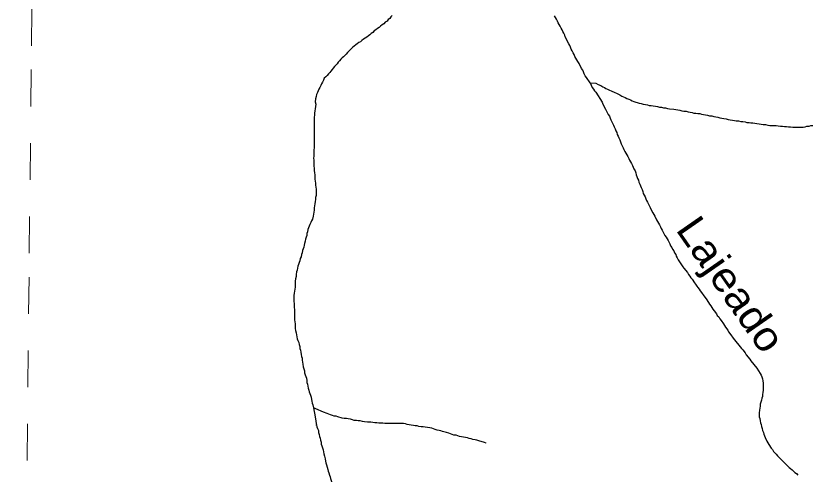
# Model space of a CAD drawing. Extents: x 652.3 to 678, y 7316.9 to 7344.9.
# Drawn here: x 652.343 to 654.508, y 7325.114 to 7326.361 of the extents above; entities that cross this region are included whole.
import ezdxf
from ezdxf.enums import TextEntityAlignment as Align

# ---------------------------------------------------------------- set-up
doc = ezdxf.new("R2010")
doc.units = 0
doc.header["$LTSCALE"] = 0.032
doc.linetypes.add('SHORT_DASHED', pattern=[2.7, 1.5, -1.2])
doc.layers.add('53', color=7, linetype='SHORT_DASHED', lineweight=13)
doc.layers.add('7', color=7, linetype='Continuous', lineweight=25)
doc.layers.add('61', color=7, linetype='Continuous')

msp = doc.modelspace()

# ---------------------------------------------------------------- linework, layer by layer
at = {"layer": '53'}
msp.add_lwpolyline([(652.343, 7322.3251), (652.3491, 7322.8901), (652.3551, 7323.4551), (652.3612, 7324.0202), (652.3672, 7324.5852), (652.3733, 7325.1502), (652.3794, 7325.7152), (652.3854, 7326.2802), (652.3915, 7326.8453), (652.3975, 7327.4103), (652.4036, 7327.9753), (652.4096, 7328.5403), (652.4157, 7329.1053), (652.4217, 7329.6703), (652.4278, 7330.2354), (652.4338, 7330.8004), (652.4399, 7331.3654), (652.4459, 7331.9304), (652.452, 7332.4954), (652.458, 7333.0604)], dxfattribs=at)
at = {"layer": '7'}
for points in [[(653.3671, 7326.3626), (653.3639, 7326.3586), (653.3608, 7326.3547), (653.3568, 7326.3515), (653.3536, 7326.3475), (653.3488, 7326.3443), (653.3448, 7326.3403), (653.3401, 7326.3372), (653.3361, 7326.3332), (653.3321, 7326.33), (653.3273, 7326.3268), (653.3234, 7326.3236), (653.3186, 7326.3204), (653.3146, 7326.3165), (653.3106, 7326.3133), (653.3067, 7326.3101), (653.3027, 7326.3069), (653.2987, 7326.3037), (653.2939, 7326.3006), (653.2891, 7326.2982), (653.2852, 7326.2942), (653.2812, 7326.291), (653.2764, 7326.2886), (653.2724, 7326.2854), (653.2685, 7326.2823), (653.2645, 7326.2791), (653.2605, 7326.2759), (653.2565, 7326.2727), (653.2533, 7326.2687)], [(653.9066, 7326.1796), (653.8963, 7326.1939), (653.8931, 7326.1987), (653.8907, 7326.2035), (653.8883, 7326.209), (653.8867, 7326.2138), (653.8835, 7326.2178), (653.8764, 7326.2321), (653.8732, 7326.2369), (653.8708, 7326.2417), (653.8676, 7326.2464), (653.8652, 7326.2512), (653.8628, 7326.256), (653.8605, 7326.2608), (653.8573, 7326.2663), (653.8549, 7326.2711), (653.8533, 7326.2759), (653.8509, 7326.2807), (653.8485, 7326.2854), (653.839, 7326.3045), (653.8374, 7326.3093), (653.835, 7326.3141), (653.8318, 7326.3189), (653.8302, 7326.3236), (653.8278, 7326.3284), (653.8254, 7326.3332), (653.8223, 7326.338), (653.8199, 7326.3427), (653.8175, 7326.3475), (653.8151, 7326.3523), (653.8119, 7326.357), (653.8095, 7326.3618)], [(653.2533, 7326.2687), (653.2494, 7326.2655), (653.2462, 7326.2616), (653.2422, 7326.2576), (653.239, 7326.2536), (653.235, 7326.2504), (653.2311, 7326.2472), (653.2279, 7326.2433), (653.2239, 7326.2393), (653.2207, 7326.2353), (653.2175, 7326.2313), (653.2144, 7326.2274), (653.2104, 7326.2234), (653.2072, 7326.2194), (653.204, 7326.2154), (653.2008, 7326.2114), (653.1976, 7326.2075), (653.1945, 7326.2035), (653.1905, 7326.1995), (653.1865, 7326.1955), (653.1825, 7326.1915), (653.1809, 7326.186), (653.1778, 7326.1812), (653.1754, 7326.1764), (653.173, 7326.1717), (653.1706, 7326.1669), (653.1682, 7326.1621), (653.1658, 7326.1573), (653.1642, 7326.1526), (653.1618, 7326.1478), (653.1602, 7326.1422), (653.1587, 7326.1358), (653.1579, 7326.1271), (653.1595, 7326.1215), (653.1587, 7326.1144), (653.1579, 7326.1088), (653.1571, 7326.1032), (653.1563, 7326.0969), (653.1563, 7326.0913), (653.1555, 7326.0857), (653.1555, 7326.0801), (653.1555, 7326.0746), (653.1555, 7326.069), (653.1555, 7326.0634), (653.1555, 7326.0579), (653.1555, 7326.0523), (653.1555, 7326.0467), (653.1555, 7326.0412), (653.1555, 7326.0356), (653.1555, 7326.03), (653.1555, 7326.0245), (653.1547, 7326.0189), (653.1547, 7326.0133), (653.1547, 7326.0077), (653.1547, 7326.0022), (653.1539, 7325.9966), (653.1539, 7325.991), (653.1539, 7325.9855), (653.1539, 7325.9799), (653.1531, 7325.9743), (653.1539, 7325.9688), (653.1539, 7325.9632), (653.1539, 7325.9576), (653.1539, 7325.952), (653.1547, 7325.9465), (653.1555, 7325.9401), (653.1563, 7325.9337), (653.1571, 7325.9282), (653.1571, 7325.9226), (653.1571, 7325.917), (653.1579, 7325.9115), (653.1587, 7325.9059), (653.1587, 7325.9003), (653.1595, 7325.8948), (653.1602, 7325.8892), (653.1602, 7325.8836), (653.1602, 7325.878), (653.1602, 7325.8725), (653.1587, 7325.8669), (653.1587, 7325.8613), (653.1579, 7325.8558), (653.1571, 7325.8494), (653.1563, 7325.8438), (653.1555, 7325.8383), (653.1547, 7325.8327), (653.1539, 7325.8271), (653.1531, 7325.8215), (653.1523, 7325.816), (653.1507, 7325.808), (653.1483, 7325.8032), (653.1459, 7325.7985), (653.1435, 7325.7937), (653.1412, 7325.7889), (653.1396, 7325.7842), (653.138, 7325.7794), (653.1372, 7325.7738), (653.1348, 7325.769), (653.1348, 7325.7635), (653.1332, 7325.7587), (653.1316, 7325.7531), (653.1308, 7325.7476)], [(653.9066, 7326.1796), (653.9217, 7326.178), (653.9289, 7326.1748), (653.936, 7326.1717), (653.9408, 7326.1685), (653.9456, 7326.1669), (653.9496, 7326.1637), (653.9543, 7326.1621), (653.9591, 7326.1589), (653.9639, 7326.1573), (653.9734, 7326.1526), (653.9782, 7326.151), (653.9878, 7326.1462), (653.9925, 7326.143), (653.9973, 7326.1414), (654.0021, 7326.139), (654.0069, 7326.1366), (654.0116, 7326.1351), (654.0164, 7326.1327), (654.0212, 7326.1303), (654.026, 7326.1287), (654.0403, 7326.1239), (654.0458, 7326.1231), (654.0514, 7326.1215), (654.057, 7326.1199), (654.0626, 7326.1191), (654.0673, 7326.1175), (654.0729, 7326.1175), (654.0785, 7326.1167), (654.0848, 7326.1152), (654.0904, 7326.1144), (654.0952, 7326.1128), (654.1008, 7326.1128), (654.1063, 7326.1112), (654.1119, 7326.1112), (654.1175, 7326.1096), (654.123, 7326.1088), (654.1342, 7326.1072), (654.1397, 7326.1064), (654.1453, 7326.1056), (654.1509, 7326.1048), (654.1564, 7326.1032), (654.162, 7326.1024), (654.1684, 7326.1016), (654.1732, 7326.1), (654.1787, 7326.0992), (654.1843, 7326.0984), (654.1891, 7326.0969), (654.1946, 7326.0969), (654.1994, 7326.0953), (654.205, 7326.0953), (654.2098, 7326.0937), (654.2153, 7326.0929), (654.2209, 7326.0921), (654.2265, 7326.0913), (654.232, 7326.0897), (654.2376, 7326.0889), (654.2432, 7326.0873), (654.2487, 7326.0865), (654.2543, 7326.0857), (654.2599, 7326.0841), (654.2655, 7326.0833), (654.271, 7326.0817), (654.2774, 7326.0809), (654.2822, 7326.0794)], [(653.9066, 7326.1796), (653.9122, 7326.1669), (653.9154, 7326.1621), (653.9185, 7326.1573), (653.9217, 7326.1534), (653.9281, 7326.1438), (653.9329, 7326.1366), (653.9392, 7326.1263), (653.9416, 7326.1215), (653.9488, 7326.1072), (653.9512, 7326.1024), (653.9559, 7326.0929), (653.9591, 7326.0881), (653.9615, 7326.0833), (653.9631, 7326.0786), (653.9679, 7326.069), (653.9703, 7326.0642), (653.9718, 7326.0595), (653.975, 7326.0539), (653.9766, 7326.0483), (653.979, 7326.0435), (653.9806, 7326.0388), (653.983, 7326.034), (653.9846, 7326.0292), (653.9878, 7326.0237), (653.9894, 7326.0181), (653.9909, 7326.0133), (653.9941, 7326.0077), (653.9965, 7326.0022), (653.9981, 7325.9974), (654.0013, 7325.9926), (654.0037, 7325.9878), (654.0061, 7325.9831), (654.0092, 7325.9783), (654.0116, 7325.9735), (654.014, 7325.9688), (654.0164, 7325.964), (654.0196, 7325.9592), (654.022, 7325.9544), (654.0236, 7325.9497), (654.026, 7325.9449), (654.0291, 7325.9393), (654.0307, 7325.9337), (654.0323, 7325.929), (654.0339, 7325.9242), (654.0355, 7325.9186), (654.0379, 7325.9138), (654.0395, 7325.9083), (654.0419, 7325.9035), (654.0435, 7325.8987), (654.0451, 7325.894), (654.0482, 7325.8884), (654.0498, 7325.8828), (654.0514, 7325.878), (654.0538, 7325.8733), (654.0562, 7325.8685), (654.0578, 7325.8637), (654.0602, 7325.8589), (654.0626, 7325.8542), (654.0697, 7325.8399), (654.0721, 7325.8351), (654.0769, 7325.8255), (654.0801, 7325.8208), (654.0825, 7325.816), (654.0872, 7325.8064), (654.0904, 7325.8017), (654.0928, 7325.7969), (654.0952, 7325.7921), (654.0984, 7325.7873), (654.1, 7325.7826), (654.1031, 7325.7778), (654.1103, 7325.7635), (654.1135, 7325.7587), (654.1159, 7325.7539), (654.1191, 7325.7499), (654.1238, 7325.7404), (654.1254, 7325.7356), (654.1286, 7325.7308), (654.131, 7325.7261), (654.1342, 7325.7213), (654.1366, 7325.7165), (654.1397, 7325.7117), (654.1413, 7325.707), (654.1437, 7325.7022), (654.1461, 7325.6974), (654.1557, 7325.6831), (654.1588, 7325.6783), (654.162, 7325.6743), (654.1716, 7325.6624)], [(654.2822, 7326.0794), (654.2877, 7326.0786), (654.2941, 7326.0778), (654.2997, 7326.077), (654.3044, 7326.0754), (654.3108, 7326.0754), (654.3172, 7326.0738), (654.3227, 7326.0738), (654.3283, 7326.073), (654.3331, 7326.0714), (654.3395, 7326.0714), (654.3442, 7326.0698), (654.3498, 7326.0698), (654.3554, 7326.069), (654.3609, 7326.0682), (654.3665, 7326.0674), (654.3721, 7326.0666), (654.3777, 7326.0658), (654.384, 7326.0658), (654.3904, 7326.0642), (654.396, 7326.0634), (654.4015, 7326.0634), (654.4071, 7326.0626), (654.4127, 7326.0626), (654.419, 7326.0618), (654.4246, 7326.0611), (654.4302, 7326.0611), (654.4357, 7326.0603), (654.4413, 7326.0603), (654.4469, 7326.0595), (654.4524, 7326.0595), (654.4588, 7326.0587), (654.4867, 7326.0587), (654.4922, 7326.0595), (654.497, 7326.0611), (654.5026, 7326.0611), (654.5073, 7326.0626), (654.5129, 7326.0626)], [(653.1308, 7325.7476), (653.1292, 7325.742), (653.1276, 7325.7372), (653.1268, 7325.7316), (653.1252, 7325.7269), (653.1236, 7325.7221), (653.1229, 7325.7165), (653.1205, 7325.7117), (653.1197, 7325.7054), (653.1173, 7325.7006), (653.1165, 7325.6942), (653.1141, 7325.6895), (653.1125, 7325.6847), (653.1109, 7325.6799), (653.1101, 7325.6743), (653.1085, 7325.6688), (653.1069, 7325.664), (653.1061, 7325.6576), (653.1061, 7325.6521), (653.1045, 7325.6457), (653.1038, 7325.6393), (653.103, 7325.6338), (653.103, 7325.6282), (653.103, 7325.6226), (653.1022, 7325.6171), (653.1014, 7325.6115), (653.1006, 7325.6059), (653.0998, 7325.6003), (653.0998, 7325.5948), (653.0998, 7325.5892), (653.0998, 7325.5836), (653.1006, 7325.5781), (653.1006, 7325.5725), (653.1006, 7325.5669), (653.1014, 7325.5614), (653.1014, 7325.5558), (653.1014, 7325.5502), (653.1014, 7325.5446), (653.1014, 7325.5391), (653.1014, 7325.5335), (653.1022, 7325.5279), (653.103, 7325.5224), (653.1038, 7325.516), (653.1038, 7325.5104), (653.1045, 7325.5049), (653.1061, 7325.4985), (653.1069, 7325.4929), (653.1077, 7325.4874), (653.1085, 7325.4818), (653.1109, 7325.477), (653.1133, 7325.4722), (653.1141, 7325.4667), (653.1157, 7325.4611), (653.1165, 7325.4555), (653.1181, 7325.4508), (653.1189, 7325.4452), (653.1197, 7325.4396), (653.1205, 7325.434), (653.1221, 7325.4293), (653.1229, 7325.4237), (653.1236, 7325.4181), (653.1244, 7325.4126), (653.1252, 7325.4054), (653.1268, 7325.3998), (653.1284, 7325.3951), (653.1292, 7325.3895), (653.1308, 7325.3839), (653.1324, 7325.3791), (653.134, 7325.3744), (653.1348, 7325.3688), (653.1356, 7325.3632), (653.1372, 7325.3585), (653.138, 7325.3529), (653.1388, 7325.3473), (653.1404, 7325.3425), (653.1419, 7325.3378), (653.1435, 7325.333), (653.1451, 7325.3282), (653.1467, 7325.3227), (653.1475, 7325.3171), (653.1491, 7325.3123), (653.1499, 7325.3067), (653.1515, 7325.302), (653.1531, 7325.294)], [(654.1716, 7325.6624), (654.1748, 7325.6576), (654.1779, 7325.6529), (654.1811, 7325.6481), (654.1843, 7325.6441), (654.1907, 7325.6346), (654.1938, 7325.6306), (654.197, 7325.6258), (654.2002, 7325.6218), (654.2034, 7325.6171), (654.2066, 7325.6123), (654.2098, 7325.6083), (654.2161, 7325.5988), (654.2225, 7325.5908), (654.2289, 7325.5813), (654.232, 7325.5765), (654.2352, 7325.5717), (654.2384, 7325.5677), (654.2408, 7325.563), (654.244, 7325.5582), (654.2503, 7325.5502), (654.2527, 7325.5454), (654.2567, 7325.5415), (654.2599, 7325.5367), (654.2631, 7325.5319), (654.2694, 7325.5224), (654.2726, 7325.5184), (654.275, 7325.5136), (654.2814, 7325.5057), (654.2838, 7325.5009), (654.2901, 7325.4929), (654.2965, 7325.4834), (654.3188, 7325.4555), (654.322, 7325.4516), (654.3283, 7325.4436), (654.3315, 7325.4388), (654.341, 7325.4269), (654.3442, 7325.4221), (654.3601, 7325.4022), (654.3697, 7325.3879), (654.3721, 7325.3831), (654.3745, 7325.3784), (654.3761, 7325.3728), (654.3769, 7325.3672), (654.3777, 7325.3616), (654.3777, 7325.3417), (654.3769, 7325.3362), (654.3761, 7325.3306), (654.3761, 7325.325), (654.3737, 7325.3203), (654.3729, 7325.3147), (654.3713, 7325.3099), (654.3697, 7325.3044), (654.3697, 7325.2988), (654.3681, 7325.2876), (654.3673, 7325.2805), (654.3673, 7325.2693), (654.3689, 7325.2646), (654.3697, 7325.259), (654.3705, 7325.2534), (654.3721, 7325.2487), (654.3729, 7325.2431), (654.3753, 7325.2375), (654.3761, 7325.2319), (654.3784, 7325.2272), (654.38, 7325.2224), (654.3816, 7325.2176), (654.3832, 7325.2128), (654.388, 7325.2033), (654.3904, 7325.1985), (654.3928, 7325.1938), (654.3991, 7325.1842), (654.4031, 7325.1802), (654.4063, 7325.1755), (654.4095, 7325.1715), (654.4135, 7325.1675), (654.4166, 7325.1635), (654.4365, 7325.1436), (654.4405, 7325.1396), (654.4485, 7325.1317), (654.4524, 7325.1285), (654.4564, 7325.1253), (654.4604, 7325.1213), (654.4644, 7325.1182), (654.4684, 7325.115), (654.4723, 7325.111)], [(653.6239, 7325.1976), (653.6231, 7325.1979), (653.6186, 7325.1993), (653.6034, 7325.2041), (653.5979, 7325.2057), (653.5931, 7325.2073), (653.5875, 7325.2081), (653.5828, 7325.2097), (653.5772, 7325.2105), (653.5724, 7325.2121), (653.5668, 7325.2128), (653.5621, 7325.2144), (653.5565, 7325.2152), (653.5509, 7325.216), (653.5462, 7325.2176), (653.5414, 7325.2192), (653.5358, 7325.22), (653.5215, 7325.2248), (653.5159, 7325.2264), (653.5048, 7325.2296), (653.5, 7325.2311), (653.4952, 7325.2327), (653.4897, 7325.2335), (653.4849, 7325.2351), (653.4801, 7325.2367), (653.4753, 7325.2383), (653.4698, 7325.2399), (653.4642, 7325.2407), (653.4578, 7325.2415), (653.4523, 7325.2423), (653.4467, 7325.2423), (653.4403, 7325.2431), (653.4356, 7325.2447), (653.43, 7325.2447), (653.4252, 7325.2463), (653.4196, 7325.2471), (653.4141, 7325.2479), (653.4085, 7325.2487), (653.4037, 7325.2502), (653.3982, 7325.251), (653.348, 7325.251), (653.3425, 7325.2518), (653.3313, 7325.2518), (653.3258, 7325.2534), (653.3202, 7325.2534), (653.3146, 7325.2542), (653.309, 7325.255), (653.3003, 7325.255), (653.2923, 7325.2558), (653.2868, 7325.2566), (653.2804, 7325.2582), (653.2748, 7325.2582), (653.2701, 7325.2598), (653.2645, 7325.2598), (653.2597, 7325.2614), (653.2541, 7325.263), (653.2478, 7325.2638), (653.243, 7325.2654), (653.2366, 7325.2654), (653.2311, 7325.2662), (653.2199, 7325.2693), (653.2152, 7325.2709), (653.2096, 7325.2717), (653.2048, 7325.2733), (653.2, 7325.2749), (653.1953, 7325.2765), (653.1905, 7325.2789), (653.1809, 7325.2821), (653.1593, 7325.2913), (653.1531, 7325.294)], [(653.1531, 7325.294), (653.1531, 7325.294), (653.1576, 7325.2696)], [(653.1576, 7325.2696), (653.1618, 7325.2463), (653.1618, 7325.2479), (653.1626, 7325.2423), (653.1642, 7325.2375), (653.1666, 7325.2319), (653.1674, 7325.2264), (653.169, 7325.2216), (653.1698, 7325.216), (653.1714, 7325.2113), (653.1722, 7325.2057), (653.1738, 7325.2009), (653.1746, 7325.1953), (653.1762, 7325.1906), (653.1778, 7325.185), (653.1793, 7325.1794), (653.1809, 7325.1739), (653.1817, 7325.1683)], [(653.1817, 7325.1683), (653.1833, 7325.1627), (653.1849, 7325.1548), (653.1857, 7325.1492), (653.1873, 7325.1444), (653.1889, 7325.1388), (653.1905, 7325.1325), (653.1921, 7325.1261), (653.1937, 7325.1213), (653.1953, 7325.1166), (653.1968, 7325.111), (653.1984, 7325.1062), (653.2, 7325.1015), (653.2016, 7325.0959), (653.2032, 7325.0895), (653.2048, 7325.0847), (653.2056, 7325.0792), (653.2072, 7325.0736), (653.2088, 7325.0688), (653.2112, 7325.0641), (653.2128, 7325.0585), (653.2144, 7325.0537), (653.2167, 7325.0489), (653.2181, 7325.0448)]]:
    msp.add_lwpolyline(points, dxfattribs=at)

# ---------------------------------------------------------------- texts
at = {"layer": '61', "width": 1.1}
msp.add_text('Lajeado', height=0.08, rotation=304.848, dxfattribs=at).set_placement((654.2574, 7325.6078), align=Align.CENTER)

doc.saveas('drawing.dxf')
